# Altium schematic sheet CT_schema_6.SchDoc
size 287 x 160 mm
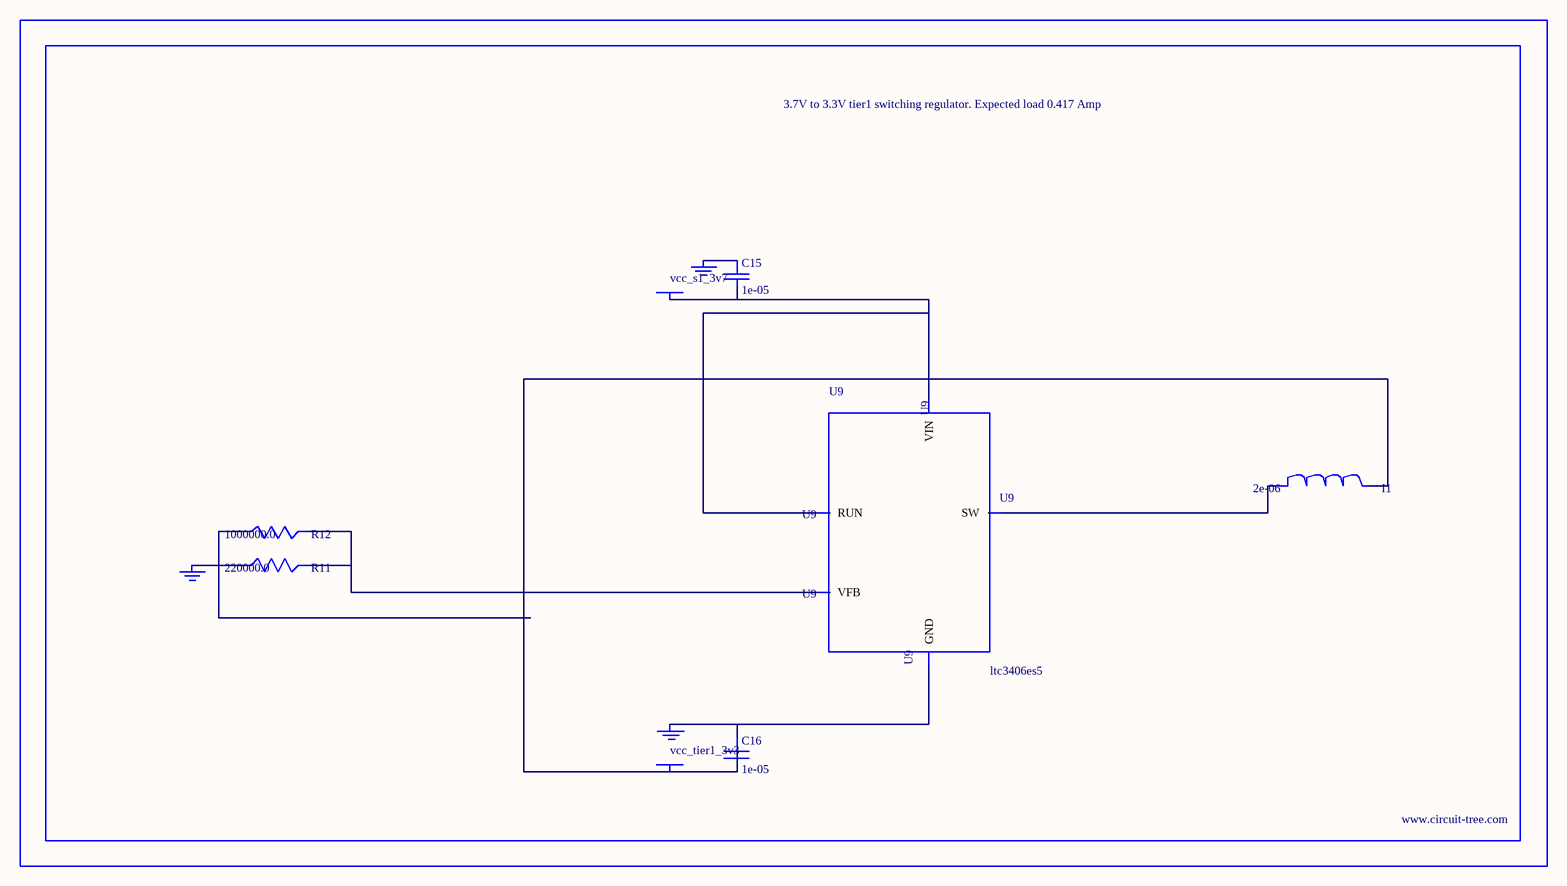
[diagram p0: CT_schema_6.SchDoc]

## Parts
BORDER5  (no value)
C15  1e-05  [C0805]
C16  1e-05  [C0805]
GND_INSTANCE_5_0  (no value)
GND_INSTANCE_5_1  (no value)
GND_INSTANCE_5_2  (no value)
I1  2e-06  [WE-HCI_7030/7040/7050]
POWER_INSTANCE_5_0  vcc_tier1_3v3
POWER_INSTANCE_5_1  vcc_s1_3v7
R11  220000.0  [R0603]
R12  1000000.0  [R0603]
U9  ltc3406es5  [TSOT-23-5]

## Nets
NetC15_1: C15.1 GND_INSTANCE_5_1.0(GND)
NetC15_2: C15.2 POWER_INSTANCE_5_1.0(PWR) U9.1(RUN) U9.4(VIN)
NetC16_1: C16.1 GND_INSTANCE_5_0.0(GND) U9.2(GND)
NetC16_2: C16.2 I1.2 POWER_INSTANCE_5_0.0(PWR) R12.1
NetGND_INSTANCE_5_2_0: GND_INSTANCE_5_2.0(GND) R11.1
NetI1_1: I1.1 U9.3(SW)
NetR11_2: R11.2 R12.2 U9.5(VFB)

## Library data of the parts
BORDER5 = BORDER_PAGE5
C15 C16 = C0805C106K8RACTU
GND_INSTANCE_5_0-GND_INSTANCE_5_2 = GND
I1 = 744314200
POWER_INSTANCE_5_0 POWER_INSTANCE_5_1 = PWR
R11 = RC0603JR-07220KL
R12 = RC0603JR-071ML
